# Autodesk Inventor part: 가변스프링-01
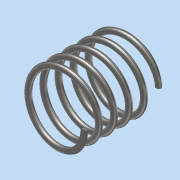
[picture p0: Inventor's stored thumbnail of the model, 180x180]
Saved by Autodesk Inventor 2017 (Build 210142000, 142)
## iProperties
Part Number: 가변스프링-01
Material: 강철, 연강
Document SubType Name: Modeling
Designer: MRC
Mass: 8.38525 g
Surface Area: 21.6626 cm^2
Volume: 1.06818 cm^3
Density: 7.85 g/cm^3
Appearance: 반연마
Author: MRC
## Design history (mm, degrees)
sketch "스케치1"
  geometry: L1 (0, 0)-(0, 26.358); L2 (0, 0)-(11, 0); L3 (0, 26.358)-(11, 26.358); C1 r 1 at (11, 0)
  constraints: 6 end point, 2 horizontal, 1 centre point, 1 coincident, 1 vertical
  dimensions: "d0" = 26.35829 distance of L1.start L1.end (derived); "d1" = 11 distance of L1.start L2.end; "d2" = 2 diameter of C1
feature "코일1" sketch "스케치1" pitch "d3" = 10; turns "d5" = 5; dims "d4" = 26.35829 (= d0), "d6" = 0, angle "d7" = 90 deg, angle "d8" = 90 deg, "d9" = 0, "d10" = 0
sketch "스케치2"
  geometry: L1 (26.358, 15)-(0, 15); L2 (0, 15)-(0, -15); L3 (0, -15)-(26.358, -15); L4 (26.358, -15)-(26.358, 15); 2 further points
  constraints: 8 end point, 2 parallel, 1 coincident, 1 horizontal, 1 midpoint, 1 perpendicular
  dimensions: "d11" = 26.35829 distance of L1.start L1.end (= d0); "d12" = 30 distance of L3.end L1.start
extrude "돌출1" sketch "스케치2" stored distance "d13" = 0; taper "d14" = 0 deg
node "솔리드1"
